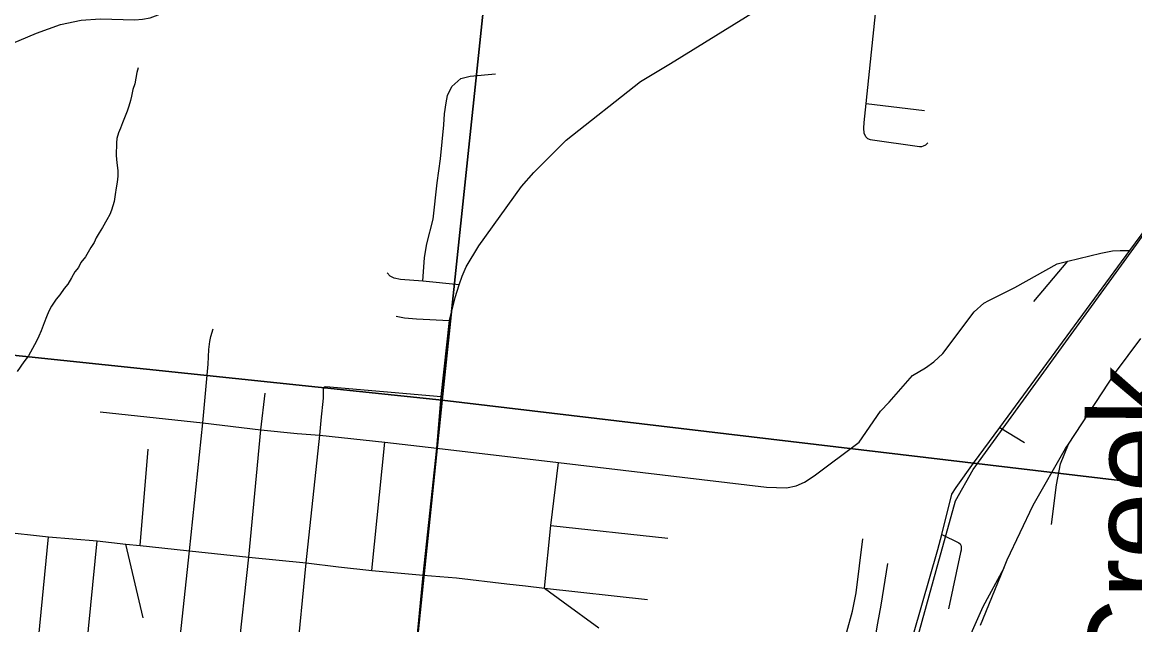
# Model space of a CAD drawing. Extents: x -8.2 to 38.5, y -0.1 to 21.9.
# Drawn here: x 4.076 to 5.256, y 14.955 to 15.594 of the extents above; entities that cross this region are included whole.
import ezdxf

# ---------------------------------------------------------------- set-up
doc = ezdxf.new("R2010")
doc.units = 0
for name, color, linetype in [('GM_X_Adjacent_County_Text', 7, 'Continuous'), ('GM_X_Airport_Location_Class_1', 7, 'Continuous'), ('GM_X_Minor_River', 7, 'Continuous'), ('GM_X_Minor_River_Text', 7, 'Continuous'), ('GM_X_Township_Subdivision_Text', 7, 'Continuous'), ('GM_X_Township_Text', 7, 'Continuous'), ('GM_X_US_Location', 7, 'Continuous')]:
    doc.layers.add(name, color=color, linetype=linetype)

msp = doc.modelspace()

# ---------------------------------------------------------------- linework, layer by layer
at = {"layer": 'GM_X_Adjacent_County_Text'}
for points in [[(4.6267, 16.1928), (4.5212, 15.1931), (3.5428, 15.2954), (3.6356, 16.3025)], [(4.6267, 16.1928), (5.6225, 16.0867), (5.5208, 15.0744), (4.5212, 15.1931)], [(3.5428, 15.2954), (4.5212, 15.1931), (4.4166, 14.1829), (3.4423, 14.2958)], [(5.5208, 15.0744), (5.4096, 14.1041), (5.3356, 14.1149), (5.2909, 14.1152), (5.217, 14.1154), (5.198, 14.1143), (5.1802, 14.1143), (5.1428, 14.1148), (5.1257, 14.114), (5.0999, 14.1135), (5.0844, 14.1123), (5.0635, 14.1102), (5.0544, 14.1088), (5.0429, 14.1065), (4.4166, 14.1829), (4.5212, 15.1931)]]:
    msp.add_lwpolyline(points, close=True, dxfattribs=at)
at = {"layer": 'GM_X_Airport_Location_Class_1'}
msp.add_lwpolyline([(4.0518, 15.0538), (4.1035, 15.0481), (4.1553, 15.0436), (4.1855, 15.0402), (4.2008, 15.0387), (4.2238, 15.0363), (4.2531, 15.0333), (4.316, 15.0264), (4.3771, 15.0205), (4.4112, 15.0163), (4.4467, 15.0122), (4.5011, 15.0075), (4.5364, 15.0044), (4.59, 14.9981), (4.6096, 14.9961), (4.63, 14.9935), (4.6497, 14.9791), (4.6875, 14.9514)], dxfattribs=at)
at = {"layer": 'GM_X_Minor_River'}
msp.add_lwpolyline([(4.1987, 15.5454), (4.1974, 15.5405), (4.1961, 15.5345), (4.1952, 15.5284), (4.1931, 15.5224), (4.1918, 15.5155), (4.1905, 15.5106), (4.1888, 15.5046), (4.1872, 15.4993), (4.1823, 15.4872), (4.1799, 15.4816), (4.1778, 15.4763), (4.1761, 15.4703), (4.1756, 15.4657), (4.1753, 15.4524), (4.1762, 15.4448), (4.1771, 15.4364), (4.1773, 15.4306), (4.1764, 15.4242), (4.1755, 15.4181), (4.1745, 15.4109), (4.1732, 15.4037), (4.1719, 15.3992), (4.1703, 15.3943), (4.1686, 15.3897), (4.1654, 15.3841), (4.161, 15.3762), (4.1574, 15.3703), (4.1543, 15.365), (4.1522, 15.3601), (4.1487, 15.3549), (4.1427, 15.3448), (4.138, 15.3388), (4.1355, 15.3335), (4.1316, 15.3291), (4.128, 15.3227), (4.124, 15.316), (4.1201, 15.3115), (4.1157, 15.3048), (4.1118, 15.2999), (4.1067, 15.2928), (4.1039, 15.2872), (4.1014, 15.2812), (4.099, 15.2751), (4.0957, 15.2665), (4.0933, 15.2608), (4.0908, 15.2556), (4.0824, 15.2398), (4.0773, 15.2335), (4.0702, 15.2234)], dxfattribs=at)
at = {"layer": 'GM_X_Township_Subdivision_Text'}
for p, q in [((4.971, 15.5075), (5.0332, 15.5002)), ((5.1492, 15.2975), (5.1853, 15.3402)), ((4.3978, 15.2074), (4.5203, 15.1968)), ((5.113, 15.164), (5.1393, 15.1479)), ((4.4467, 15.0122), (4.4605, 15.1484)), ((4.2008, 15.0387), (4.2095, 15.1409)), ((4.6367, 15.0599), (4.7608, 15.0465)), ((4.0813, 14.821), (4.1035, 15.0481)), ((4.2039, 14.962), (4.1855, 15.0402)), ((4.63, 14.9935), (4.7391, 14.9816))]:
    msp.add_line(p, q, dxfattribs=at)
for points in [[(4.9707, 15.4724), (4.9689, 15.476), (4.9688, 15.4814), (4.9692, 15.4874), (4.971, 15.5075), (4.9869, 15.6574), (4.9902, 15.6986), (5.0035, 15.8054)], [(4.5007, 15.319), (4.5024, 15.3441), (4.5049, 15.3587), (4.5116, 15.3848), (4.5159, 15.4233), (4.5196, 15.449), (4.523, 15.4849), (4.5238, 15.4967), (4.5254, 15.5082), (4.527, 15.5162), (4.5317, 15.5257), (4.5411, 15.534), (4.5511, 15.5365), (4.5779, 15.5392)], [(4.9707, 15.4724), (4.9727, 15.4706), (4.9754, 15.4693), (5.0277, 15.4619), (5.0303, 15.4621), (5.0321, 15.4628), (5.0344, 15.4638), (5.0365, 15.466)], [(4.1583, 15.1806), (4.2675, 15.169), (4.3289, 15.1614), (4.3673, 15.1576), (4.3915, 15.1557), (4.4605, 15.1484), (4.5158, 15.1422), (4.6448, 15.1268), (4.8654, 15.1008), (4.8868, 15.0998), (4.8969, 15.1021), (4.9058, 15.1058), (4.9159, 15.1127), (4.9638, 15.1483), (4.9863, 15.1813), (4.9957, 15.1907), (5.0204, 15.2192), (5.0343, 15.2271), (5.0428, 15.2336), (5.0526, 15.2424), (5.0859, 15.2868), (5.0959, 15.2957), (5.1015, 15.2985), (5.1218, 15.3088), (5.1289, 15.3123), (5.1737, 15.3374), (5.1853, 15.3402), (5.22, 15.3488), (5.2326, 15.3514), (5.2406, 15.3515), (5.251, 15.3515)], [(4.5393, 15.3152), (4.5007, 15.319), (4.4772, 15.3208), (4.4705, 15.3223), (4.466, 15.3246), (4.4628, 15.328)], [(4.4726, 15.282), (4.4815, 15.2802), (4.4941, 15.2792), (4.5292, 15.2774)], [(4.2428, 14.932), (4.2428, 14.9353), (4.2433, 14.941), (4.2531, 15.0333), (4.2675, 15.169), (4.273, 15.2312), (4.2737, 15.2466), (4.2747, 15.2553), (4.2758, 15.2605), (4.2782, 15.2686)], [(4.3536, 14.7844), (4.3668, 14.915), (4.3771, 15.0205), (4.3915, 15.1557), (4.3933, 15.1752), (4.3949, 15.1915), (4.3953, 15.1954), (4.3954, 15.2009), (4.3955, 15.2048), (4.3961, 15.207), (4.3978, 15.2074)], [(4.2683, 14.5887), (4.2896, 14.7793), (4.2916, 14.7919), (4.3044, 14.9197), (4.316, 15.0264), (4.3289, 15.1614), (4.3334, 15.2004)], [(4.63, 14.9935), (4.6367, 15.0599), (4.6448, 15.1268)], [(5.0513, 15.0503), (5.0695, 15.0417), (5.0708, 15.0404), (5.0715, 15.0393), (5.0719, 15.0375), (5.0718, 15.0338), (5.0713, 15.0314), (5.0587, 14.9717)], [(4.0573, 14.1626), (4.0984, 14.5037), (4.1001, 14.5204), (4.1098, 14.6072), (4.1178, 14.6816), (4.1244, 14.7511), (4.1327, 14.8141), (4.1553, 15.0436)], [(4.8806, 14.6948), (4.8771, 14.7141), (4.8766, 14.7199), (4.8774, 14.7248), (4.8795, 14.732), (4.8985, 14.7761), (4.9185, 14.8222), (4.9217, 14.8339), (4.9266, 14.8539), (4.9274, 14.8571), (4.9387, 14.9033), (4.9568, 14.9693), (4.9606, 14.9886), (4.9678, 15.0457)], [(4.954, 14.8533), (4.9773, 14.9211), (4.9775, 14.9223), (4.9781, 14.9257), (4.9834, 14.9563), (4.9872, 14.9755), (4.9942, 15.0198)]]:
    msp.add_lwpolyline(points, dxfattribs=at)
at = {"layer": 'GM_X_Township_Text'}
for points in [[(4.0311, 15.5571), (4.091, 15.5821), (4.1165, 15.5913), (4.1383, 15.596), (4.1583, 15.5973), (4.1951, 15.5963), (4.2035, 15.5971), (4.2116, 15.5986), (4.2198, 15.6015), (4.2279, 15.6057), (4.2342, 15.6107), (4.2392, 15.616), (4.2484, 15.6273), (4.2684, 15.6575), (4.2938, 15.6929), (4.3159, 15.7258), (4.3285, 15.7418), (4.3375, 15.751), (4.3681, 15.7848), (4.3693, 15.7863)], [(4.4451, 14.49), (4.4529, 14.5695), (4.4763, 14.7514), (4.4779, 14.7765), (4.4897, 14.8901), (4.5011, 15.0075), (4.5158, 15.1422), (4.5203, 15.1968), (4.5292, 15.2774), (4.5351, 15.3018), (4.5372, 15.3086), (4.5393, 15.3152), (4.5426, 15.3245), (4.5469, 15.3344), (4.5601, 15.3566), (4.6055, 15.4196), (4.6187, 15.4344), (4.653, 15.4688), (4.7317, 15.5308), (4.7637, 15.5501), (4.8672, 15.6139)], [(4.8744, 14.4535), (4.8881, 14.5023), (4.8991, 14.5492), (4.9053, 14.576), (4.9214, 14.6356), (4.9267, 14.6901), (4.9338, 14.7399), (4.9512, 14.7638), (4.9774, 14.8158), (5.0074, 14.8965), (5.0132, 14.9166), (5.0473, 15.0347), (5.0513, 15.0503), (5.0622, 15.0931), (5.0666, 15.1002), (5.0852, 15.1262), (5.113, 15.164), (5.251, 15.3515), (5.3071, 15.4277), (5.3298, 15.4642), (5.378, 15.5444), (5.4003, 15.5859), (5.4126, 15.6094)]]:
    msp.add_lwpolyline(points, dxfattribs=at)
at = {"layer": 'GM_X_US_Location'}
for points in [[(4.8726, 14.4523), (4.9232, 14.6599), (4.9312, 14.7407), (4.9581, 14.7787), (4.9894, 14.8466), (5.0205, 14.9215), (5.0456, 15.0123), (5.0661, 15.0863), (5.0847, 15.1193), (5.258, 15.3581), (5.3154, 15.438), (5.3904, 15.5758), (5.4018, 15.5913)], [(5.1858, 15.1464), (5.2356, 15.2222), (5.2625, 15.2585)], [(5.1173, 15.0148), (5.1209, 15.0237), (5.1485, 15.0814), (5.1828, 15.1418), (5.1858, 15.1464)], [(5.1679, 15.0611), (5.1731, 15.1033), (5.1773, 15.1255), (5.1858, 15.1464)], [(5.1173, 15.0148), (5.0949, 14.9736), (5.0836, 14.9482), (5.0788, 14.9336)], [(5.0925, 14.9542), (5.1173, 15.0148)]]:
    msp.add_lwpolyline(points, dxfattribs=at)

# ---------------------------------------------------------------- texts
at = {"layer": 'GM_X_Minor_River_Text'}
msp.add_text('Creek', height=0.09472, rotation=89.6595, dxfattribs=at).set_placement((5.3009, 14.8908))

doc.saveas('drawing.dxf')
